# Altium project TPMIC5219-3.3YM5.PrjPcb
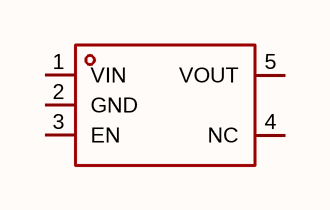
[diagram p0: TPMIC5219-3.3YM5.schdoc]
1 sheet, 1 parts. Net scope: global (net labels, ports and power ports of the same name join across sheets).

## Sheet TPMIC5219-3.3YM5.schdoc
size 127 x 101 mm

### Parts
U?  tpmic5219-3.3ym5  [SOT-23-5_L2.9-W1.6-P0.95-LS2.8-BR]  (value not drawn)

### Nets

Not connected (* = marked no-connect by the designer): U? 1(VIN) 2(GND) 3(EN) 4(NC) 5(VOUT)

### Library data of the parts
U? = tpmic5219-3.3ym5: 输出极性:正极;工作电压:20V;输出电压:3.3V;输出电流:500mA;电源纹波抑制比(PSRR):70dB@(1kHz);输出类型:固定;; Manufacturer: TECH PUBLIC(台舟); AddInBom: yes; ModelId: 7ba65df16e7b4570af156e925f9c37fe; ModelTransform: 114.173,114.173,0,90,0,0,0,0,0; Output Configuration: 正极; Voltage - Supply: 20V; Output Voltage: 3.3V; Output Current: 500mA; Voltage Dropout: 420mV@(100mA); standby current: 1.5uA; Output Type: 固定; Number of Outputs: 1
